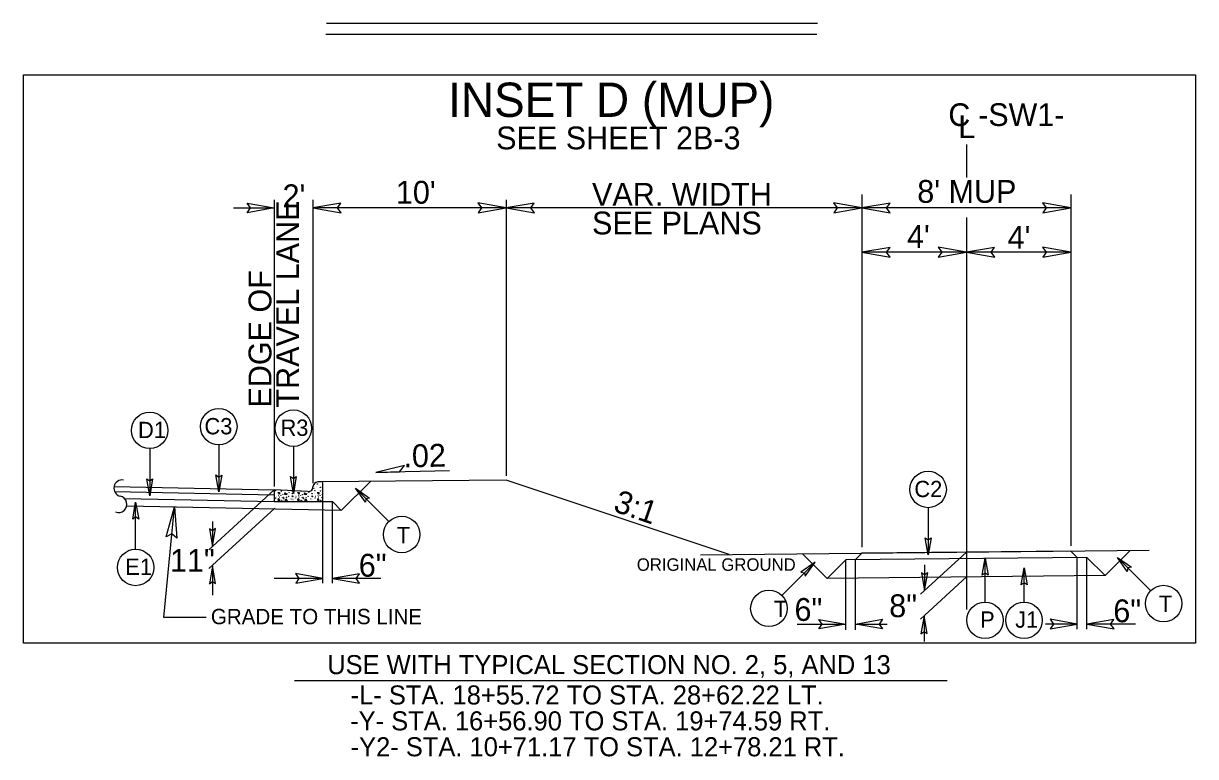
# Model space of a CAD drawing. Extents: x 958711 to 962106, y 831169 to 840840.
# Drawn here: x 959306.8 to 959707.2, y 838809.6 to 839060.1 of the extents above; entities that cross this region are included whole.
import ezdxf

# ---------------------------------------------------------------- set-up
doc = ezdxf.new("R2010")
doc.units = 0
for name, color, linetype in [('Default', 7, 'Continuous'), ('Old_Level_1', 7, 'Continuous'), ('Old_Level_11', 7, 'Continuous'), ('Old_Level_21', 7, 'Continuous'), ('Old_Level_3', 7, 'Continuous'), ('Prop Dimension Text', 7, 'Continuous'), ('Typical ID Circle CELL', 7, 'Continuous'), ('Typical Terminator CELL', 7, 'Continuous'), ('Typical Text ID Circle CELL', 7, 'Continuous')]:
    doc.layers.add(name, color=color, linetype=linetype)

msp = doc.modelspace()

# ---------------------------------------------------------------- linework, layer by layer
at = {"layer": 'Default'}
for p, q in [((959628.9, 839018.7), (959628.9, 839007.39)), ((959628.9, 838993.73), (959628.9, 838859.89))]:
    msp.add_line(p, q, dxfattribs=at)
at = {"layer": 'Old_Level_1'}
for p, q in [((959578.04, 839060.06), (959410.34, 839060.06)), ((959577.76, 839056.25), (959410.06, 839056.25)), ((959392.43, 838999.76), (959392.43, 838901.85)), ((959405.64, 838999.76), (959405.64, 838903.05)), ((959471.68, 838999.76), (959471.68, 838905.52)), ((959593.2, 839001.65), (959593.2, 838881.16)), ((959664.59, 839001.65), (959664.59, 838881.55)), ((959378.56, 838997.03), (959392.43, 838997.03)), ((959471.68, 838997.03), (959405.64, 838997.03)), ((959593.2, 838997.03), (959471.68, 838997.03)), ((959664.59, 838997.03), (959593.2, 838997.03)), ((959628.9, 838981.88), (959593.2, 838981.88)), ((959664.59, 838981.88), (959628.9, 838981.88)), ((959452.29, 838907.17), (959427.18, 838906.67)), ((959471.68, 838904.03), (959408.72, 838903.4)), ((959415.37, 838893.64), (959425.3, 838903.57)), ((959547.91, 838878.62), (959471.68, 838904.03)), ((959337.74, 838901.86), (959392.43, 838900.75)), ((959337.92, 838900.13), (959392.43, 838899.03)), ((959392.43, 838900.75), (959370.11, 838880.21)), ((959341.26, 838897.81), (959392.43, 838896.77)), ((959342.08, 838895.29), (959415.38, 838893.81)), ((959354.78, 838857.11), (959358.37, 838894.96)), ((959392.62, 838894.51), (959370.11, 838873.8)), ((959409.01, 838896.77), (959412.31, 838896.7)), ((959409.01, 838868.87), (959409.01, 838896.49)), ((959412.31, 838896.7), (959415.37, 838893.64)), ((959412.31, 838868.87), (959412.31, 838896.49)), ((959371.37, 838889.88), (959371.37, 838881.37)), ((959538.02, 838878.52), (959691.35, 838880.06)), ((959572.94, 838878.87), (959581.34, 838870.48)), ((959593.2, 838879.07), (959591, 838876.87)), ((959664.59, 838879.79), (959593.2, 838879.07)), ((959628.9, 838879.43), (959613.25, 838865.04)), ((959664.59, 838879.79), (959666.75, 838877.63)), ((959684.85, 838879.99), (959676.29, 838871.43)), ((959371.39, 838874.74), (959371.39, 838864.78)), ((959587.7, 838876.84), (959581.34, 838870.48)), ((959670.05, 838877.66), (959587.7, 838876.84)), ((959587.7, 838852.92), (959587.7, 838876.84)), ((959591, 838852.92), (959591, 838876.87)), ((959614.63, 838875.05), (959614.63, 838866.3)), ((959666.75, 838853.09), (959666.75, 838877.63)), ((959670.05, 838877.66), (959676.29, 838871.43)), ((959670.05, 838853.09), (959670.05, 838877.66)), ((959409.01, 838870.46), (959392.41, 838870.46)), ((959428.91, 838870.46), (959412.31, 838870.46)), ((959676.29, 838871.43), (959581.34, 838870.48)), ((959628.9, 838870.95), (959613.25, 838856.55)), ((959369.21, 838857.11), (959354.78, 838857.11)), ((959571.1, 838854.88), (959587.7, 838854.88)), ((959591, 838854.88), (959601.79, 838854.88)), ((959614.46, 838857.67), (959614.46, 838848.94)), ((959666.75, 838854.88), (959655.97, 838854.88)), ((959686.65, 838854.88), (959670.05, 838854.88)), ((959399.38, 838835.56), (959622.36, 838835.56))]:
    msp.add_line(p, q, dxfattribs=at)
msp.add_lwpolyline([(959306.79, 839042.47), (959707.17, 839042.47), (959707.17, 838848.29), (959306.79, 838848.29)], close=True, dxfattribs=at)
for centre, start, end in [((959340.49, 838901.28), 79.4545, 256.8065), ((959339.31, 838895.78), 248.3355, 78.8593)]:
    msp.add_arc(centre, 2.81, start, end, dxfattribs=at)
at = {"layer": 'Old_Level_11'}
for p, q in [((959436.92, 838909.09), (959427.18, 838906.67)), ((959427.18, 838906.67), (959435.19, 838906.83)), ((959435.19, 838906.83), (959436.92, 838909.09))]:
    msp.add_line(p, q, dxfattribs=at)
for points in [[(959415.25, 838998.69), (959405.64, 838997.03), (959415.31, 838995.31), (959414.08, 838997.03)], [(959462.07, 838995.38), (959471.68, 838997.03), (959462.02, 838998.74), (959463.24, 838997.03)], [(959481.29, 838998.69), (959471.68, 838997.03), (959481.35, 838995.31), (959480.12, 838997.03)], [(959583.59, 838995.38), (959593.2, 838997.03), (959583.54, 838998.74), (959584.76, 838997.03)], [(959602.81, 838998.69), (959593.2, 838997.03), (959602.87, 838995.31), (959601.64, 838997.03)], [(959654.98, 838995.38), (959664.59, 838997.03), (959654.93, 838998.74), (959656.15, 838997.03)], [(959602.81, 838983.54), (959593.2, 838981.88), (959602.87, 838980.17), (959601.64, 838981.88)], [(959619.29, 838980.23), (959628.9, 838981.88), (959619.24, 838983.59), (959620.46, 838981.88)], [(959638.5, 838983.54), (959628.9, 838981.88), (959638.56, 838980.17), (959637.33, 838981.88)], [(959654.98, 838980.23), (959664.59, 838981.88), (959654.93, 838983.59), (959656.15, 838981.88)], [(959355.55, 838884.61), (959358.37, 838894.96), (959359.23, 838884.21), (959357.49, 838885.72)]]:
    msp.add_lwpolyline(points, close=True, dxfattribs=at)
at = {"layer": 'Old_Level_3'}
for p, q in [((959408.72, 838903.4), (959407.34, 838903.4)), ((959409.01, 838900.09), (959409.01, 838903.12)), ((959403.97, 838900.18), (959392.43, 838900.75)), ((959392.43, 838900.75), (959392.43, 838896.77)), ((959393.69, 838899.83), (959394.27, 838899.85)), ((959394.27, 838899.27), (959393.69, 838899.83)), ((959394.27, 838899.85), (959394.27, 838899.27)), ((959395.95, 838899.22), (959396.79, 838899.45)), ((959396.69, 838898.96), (959395.95, 838899.22)), ((959396.79, 838899.45), (959396.69, 838898.96)), ((959400.42, 838899.83), (959401, 838899.85)), ((959401, 838899.27), (959400.42, 838899.83)), ((959401, 838899.85), (959401, 838899.27)), ((959402.69, 838899.22), (959403.51, 838899.45)), ((959403.42, 838898.96), (959402.69, 838899.22)), ((959403.51, 838899.45), (959403.42, 838898.96)), ((959403.97, 838900.18), (959403.97, 838900.18)), ((959405.67, 838901.21), (959405.52, 838901.25)), ((959405.56, 838901.36), (959405.67, 838901.21)), ((959407.15, 838899.83), (959407.73, 838899.85)), ((959407.73, 838899.27), (959407.15, 838899.83)), ((959407.73, 838899.85), (959407.73, 838899.27)), ((959409.01, 838896.77), (959409.01, 838900.09)), ((959392.43, 838896.77), (959409.01, 838896.77)), ((959393.9, 838897.8), (959393.72, 838897.19)), ((959393.72, 838897.19), (959394.36, 838897.15)), ((959394.36, 838897.15), (959393.9, 838897.8)), ((959396.63, 838897.49), (959396.07, 838897.1)), ((959396.07, 838897.1), (959396.97, 838896.88)), ((959396.97, 838896.88), (959396.63, 838897.49)), ((959400.63, 838897.8), (959400.45, 838897.19)), ((959400.45, 838897.19), (959401.09, 838897.15)), ((959401.09, 838897.15), (959400.63, 838897.8)), ((959403.36, 838897.49), (959402.81, 838897.1)), ((959402.81, 838897.1), (959403.7, 838896.88)), ((959403.7, 838896.88), (959403.36, 838897.49)), ((959407.35, 838897.8), (959407.18, 838897.19)), ((959407.18, 838897.19), (959407.82, 838897.15)), ((959407.82, 838897.15), (959407.35, 838897.8))]:
    msp.add_line(p, q, dxfattribs=at)
for centre in [(959406.07, 838902.56), (959407.17, 838902.69), (959408.03, 838902.32), (959392.64, 838899.36), (959392.92, 838900.47), (959393.13, 838898.44), (959393.93, 838898.78), (959394.7, 838898.69), (959394.85, 838900.29), (959395.4, 838899.09), (959396.11, 838899.67), (959397.28, 838898.47), (959397.55, 838899.83), (959398.63, 838899.43), (959398.66, 838898.63), (959398.75, 838898.36), (959399.37, 838899.36), (959399.86, 838898.44), (959400.66, 838898.78), (959401.43, 838898.69), (959402.13, 838899.09), (959402.84, 838899.67), (959404.01, 838898.47), (959404.28, 838899.83), (959405.27, 838900.44), (959405.36, 838899.43), (959405.39, 838898.63), (959405.48, 838898.36), (959406.04, 838901.27), (959406.1, 838899.36), (959406.37, 838900.47), (959406.59, 838898.44), (959407.02, 838901.76), (959407.39, 838898.78), (959408.16, 838898.69), (959408.19, 838901.58), (959408.31, 838900.29), (959408.86, 838899.09), (959408.95, 838901.67), (959392.98, 838897.89), (959394.18, 838898.23), (959394.85, 838897.16), (959395.29, 838898.02), (959395.37, 838896.91), (959395.58, 838898.2), (959395.68, 838897.68), (959396.63, 838898.2), (959398.23, 838897.59), (959398.91, 838897.43), (959399.71, 838897.89), (959400.91, 838898.23), (959401.58, 838897.16), (959402.01, 838898.02), (959402.1, 838896.91), (959402.31, 838898.2), (959402.41, 838897.68), (959403.36, 838898.2), (959404.96, 838897.59), (959405.63, 838897.43), (959406.44, 838897.89), (959407.64, 838898.23), (959408.31, 838897.16), (959408.74, 838898.02), (959408.83, 838896.91)]:
    msp.add_circle(centre, 0.0432, dxfattribs=at)
for centre, radius, start, end in [((959407.35, 838901.75), 1.66, 90, 178.9266), ((959408.72, 838903.12), 0.287, 0, 90), ((959408.83, 838903.33), 0.0432, 169.6531, 280.3469), ((959398.54, 838900.44), 0.0432, 164.1199, 10.1626), ((959401.58, 838900.29), 0.0432, 162.062, 12.2205), ((959404.05, 838901.81), 1.64, 267.1376, 358.9266), ((959409.04, 838898.2), 0.0432, 150.4173, 209.5827)]:
    msp.add_arc(centre, radius, start, end, dxfattribs=at)
at = {"layer": 'Typical ID Circle CELL'}
for p, q in [((959349.92, 838914.8), (959349.92, 838898.71)), ((959373.52, 838916.08), (959373.52, 838900)), ((959398.99, 838915.57), (959398.99, 838899.48)), ((959431.6, 838889.87), (959420.23, 838901.24)), ((959345.12, 838880.42), (959345.12, 838896.51)), ((959615.82, 838894.62), (959615.82, 838878.54)), ((959565.83, 838864.62), (959577.21, 838876)), ((959635.27, 838862.4), (959635.27, 838877.32)), ((959691.86, 838866.27), (959680.48, 838877.65)), ((959648.59, 838862.4), (959648.59, 838874.06))]:
    msp.add_line(p, q, dxfattribs=at)
for centre in [(959349.92, 838921.02), (959373.52, 838922.31), (959398.99, 838921.79), (959615.82, 838900.85), (959436, 838885.46), (959345.12, 838874.2), (959561.43, 838860.22), (959696.26, 838861.87), (959635.27, 838856.17), (959648.59, 838856.17)]:
    msp.add_circle(centre, 6.23, dxfattribs=at)
at = {"layer": 'Typical Terminator CELL'}
for points in [[(959383.21, 838998.62), (959392.43, 838997.03), (959383.16, 838995.39), (959384.34, 838997.03)], [(959350.91, 838904.48), (959349.92, 838898.71), (959348.89, 838904.51), (959349.92, 838903.77)], [(959374.51, 838905.76), (959373.52, 838900), (959372.49, 838905.79), (959373.52, 838905.05)], [(959399.99, 838905.25), (959398.99, 838899.48), (959397.97, 838905.28), (959398.99, 838904.54)], [(959423.6, 838896.46), (959420.23, 838901.24), (959425.05, 838897.87), (959423.8, 838897.66)], [(959344.13, 838890.75), (959345.12, 838896.51), (959346.15, 838890.72), (959345.12, 838891.45)], [(959370.33, 838887.44), (959371.37, 838881.37), (959372.45, 838887.47), (959371.37, 838886.7)], [(959616.81, 838884.3), (959615.82, 838878.54), (959614.79, 838884.33), (959615.82, 838883.6)], [(959372.43, 838868.67), (959371.39, 838874.74), (959370.31, 838868.64), (959371.39, 838869.41)], [(959573.84, 838871.22), (959577.21, 838876), (959572.39, 838872.62), (959573.63, 838872.42)], [(959634.28, 838871.55), (959635.27, 838877.32), (959636.29, 838871.52), (959635.27, 838872.26)], [(959683.86, 838872.87), (959680.48, 838877.65), (959685.31, 838874.27), (959684.06, 838874.07)], [(959399.78, 838868.87), (959409.01, 838870.46), (959399.73, 838872.1), (959400.91, 838870.46)], [(959421.53, 838872.05), (959412.31, 838870.46), (959421.58, 838868.82), (959420.4, 838870.46)], [(959613.59, 838872.37), (959614.63, 838866.3), (959615.71, 838872.41), (959614.63, 838871.63)], [(959647.6, 838868.3), (959648.59, 838874.06), (959649.62, 838868.26), (959648.59, 838869)], [(959578.48, 838856.46), (959587.7, 838854.88), (959578.43, 838853.24), (959579.6, 838854.88)], [(959600.22, 838853.29), (959591, 838854.88), (959600.27, 838856.51), (959599.1, 838854.88)], [(959615.51, 838851.6), (959614.46, 838857.67), (959613.38, 838851.57), (959614.46, 838852.34)], [(959657.53, 838853.29), (959666.75, 838854.88), (959657.47, 838856.51), (959658.65, 838854.88)], [(959679.27, 838856.46), (959670.05, 838854.88), (959679.32, 838853.24), (959678.14, 838854.88)]]:
    msp.add_lwpolyline(points, close=True, dxfattribs=at)

# ---------------------------------------------------------------- texts
at = {"layer": 'Old_Level_1'}
for s, height, p in [('INSET D (MUP)', 11.7158, (959451.88, 839028.13)), ('GRADE TO THIS LINE', 5.2473, (959370.82, 838854.81)), ('USE WITH TYPICAL SECTION NO. 2, 5, AND 13', 6.5088, (959410.55, 838837.75)), ('-L- STA. 18+55.72 TO STA. 28+62.22 LT.', 6.5088, (959418.55, 838827.39)), ('-Y- STA. 16+56.90 TO STA. 19+74.59 RT.', 6.5088, (959418.39, 838818.54)), ('-Y2- STA. 10+71.17 TO STA. 12+78.21 RT.', 6.5088, (959418.55, 838809.69))]:
    msp.add_text(s, height=height, dxfattribs=at).set_placement(p)
at = {"layer": 'Old_Level_21'}
msp.add_text('ORIGINAL GROUND', height=4.2722, dxfattribs=at).set_placement((959516.3, 838873.05))
at = {"layer": 'Old_Level_3'}
for s, height, p in [('SEE SHEET 2B-3', 7.8009, (959468.26, 839017.04)), ("8' MUP", 7.801, (959612.11, 838998.77)), ("2'", 7.801, (959395.3, 838997.28)), ("10'", 7.801, (959434.01, 838998.48)), ('VAR. WIDTH', 7.801, (959501.01, 838997.76)), ('SEE PLANS', 7.801, (959501.01, 838987.98)), ("4'", 7.801, (959608.6, 838983.36)), ("4'", 7.801, (959642.97, 838983.11))]:
    msp.add_text(s, height=height, dxfattribs=at).set_placement(p)
for s, height, rotation, p in [('TRAVEL LANE', 7.8009, 90, (959400.92, 838928.83)), ('EDGE OF', 7.801, 90, (959391.49, 838928.83)), ('3:1', 7.801, 341.0454, (959507.92, 838893.53))]:
    msp.add_text(s, height=height, rotation=rotation, dxfattribs=at).set_placement(p)
at = {"layer": 'Prop Dimension Text'}
for s, height, rotation, p in [('C', 7.77, 0, (959622.73, 839025)), ('-SW1-', 7.767, 0, (959632.93, 839025.02)), ('L', 7.77, 0, (959626.12, 839020.91)), ('.02', 7.801, 1.1839, (959436.67, 838908.37)), ('11"', 7.801, 0, (959356.84, 838872.71)), ('6"', 7.801, 0, (959421.33, 838871.06)), ('6"', 7.801, 0, (959570.18, 838855.95)), ('8"', 7.801, 0, (959602.53, 838857.22)), ('6"', 7.801, 0, (959679.07, 838855.48))]:
    msp.add_text(s, height=height, rotation=rotation, dxfattribs=at).set_placement(p)
at = {"layer": 'Typical Text ID Circle CELL'}
for s, height, p in [('D1', 5.572, (959345.93, 838918.39)), ('C3', 5.572, (959368.63, 838919.68)), ('R3', 5.572, (959394.61, 838919.16)), ('C2', 5.572, (959611.12, 838898.22)), ('T', 5.57, (959434.3, 838882.49)), ('E1', 5.572, (959341.58, 838871.64)), ('T', 5.57, (959694.64, 838859.01)), ('P', 5.57, (959633.59, 838853.61)), ('J1', 5.572, (959645.56, 838853.61))]:
    msp.add_text(s, height=height, dxfattribs=at).set_placement(p)
msp.add_text('T', height=5.57, rotation=360, dxfattribs=at).set_placement((959563.14, 838857.24))

doc.saveas('drawing.dxf')
